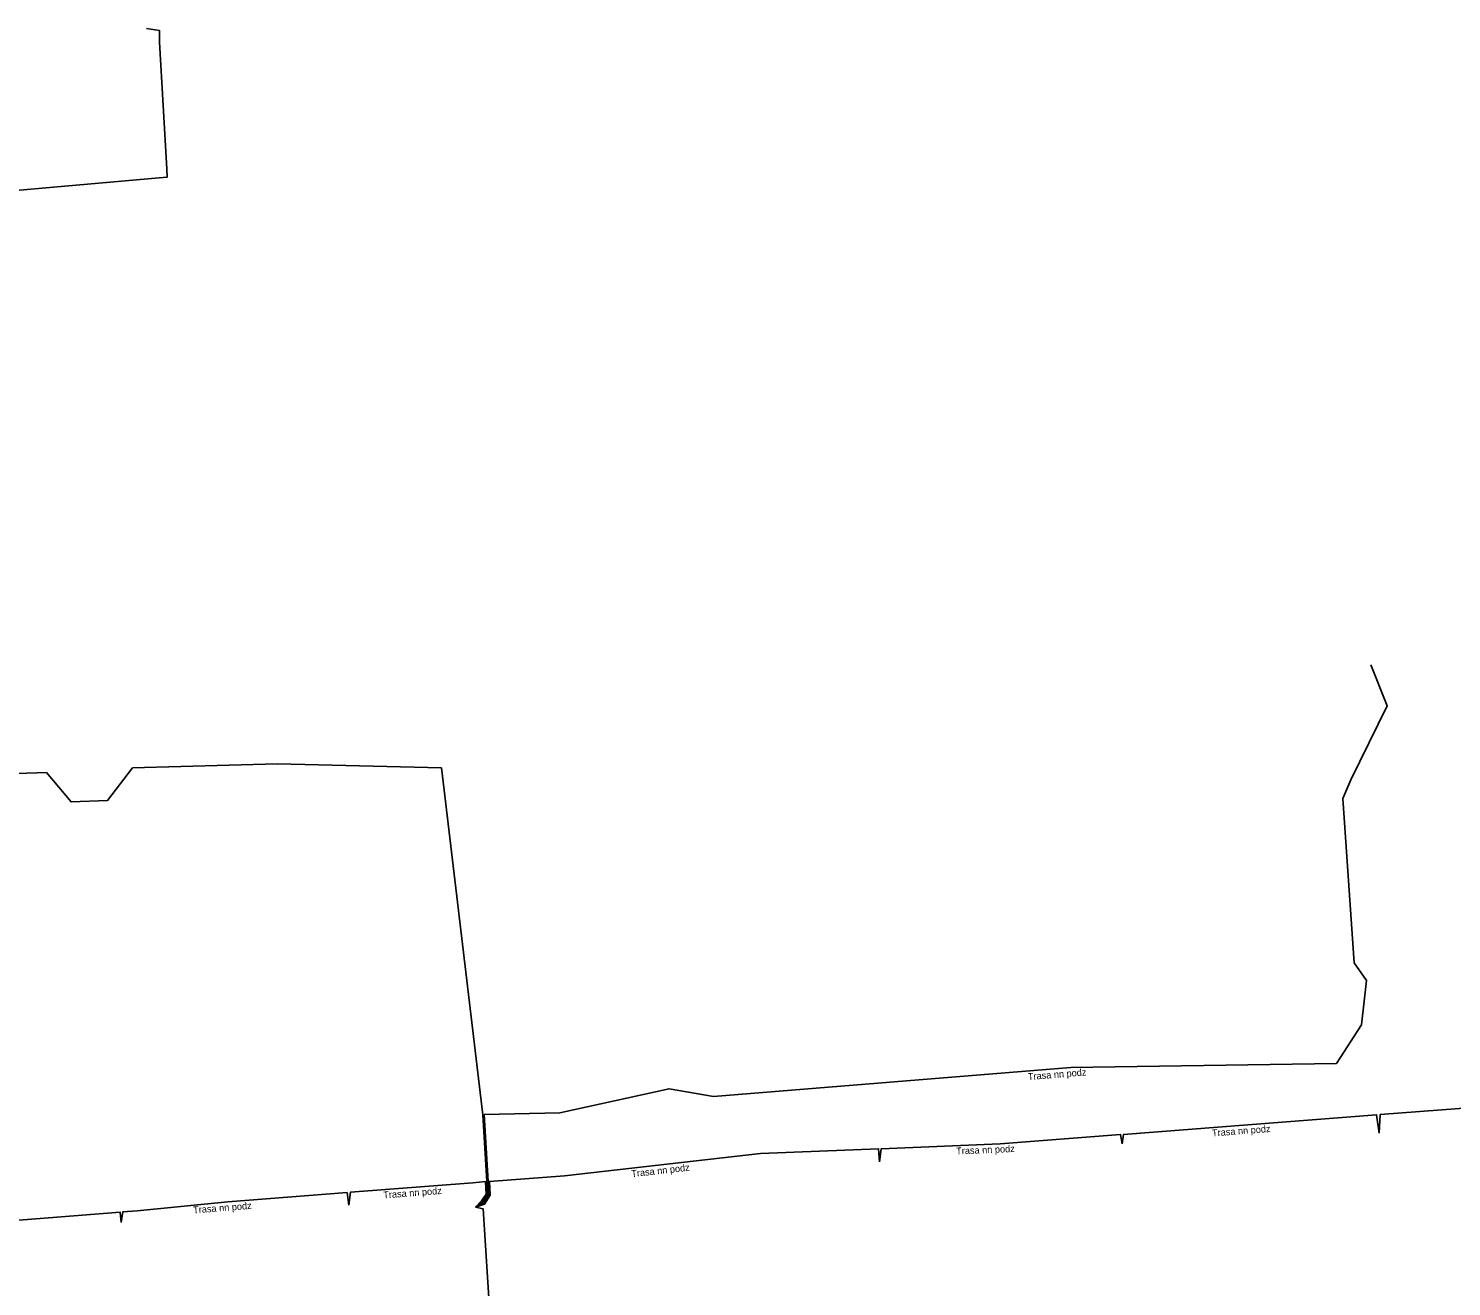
# Model space of a CAD drawing. Extents: x -873583 to -872966, y -1012951 to -1012536.
# Drawn here: x -873321.7 to -873218, y -1012640.4 to -1012548.7 of the extents above; entities that cross this region are included whole.
import ezdxf

# ---------------------------------------------------------------- set-up
doc = ezdxf.new("R2010")
doc.units = 0
doc.layers.add('Popiskový text - Ostatní atributy Trasy', color=7, linetype='Continuous')
doc.layers.add('Spojnice NN', color=7, linetype='Continuous')

msp = doc.modelspace()

# ---------------------------------------------------------------- linework, layer by layer
at = {"layer": 'Spojnice NN'}
for points in [[(-873330.33, -1012561.17), (-873312.15, -1012559.56), (-873311.56, -1012559.51), (-873311.59, -1012558.92), (-873312.14, -1012549.68), (-873312.13, -1012548.83), (-873313.07, -1012548.68)], [(-873289.09, -1012634.63), (-873288.49, -1012634.3), (-873288.13, -1012633.72), (-873288.17, -1012632.75), (-873288.46, -1012627.87), (-873282.96, -1012627.74), (-873274.99, -1012625.99), (-873271.74, -1012626.56), (-873245.69, -1012624.45), (-873226.34, -1012624.15), (-873224.52, -1012621.32), (-873224.14, -1012618.09), (-873225.06, -1012616.8), (-873225.88, -1012604.82), (-873225.28, -1012603.47), (-873222.64, -1012598.07), (-873223.83, -1012595.09)], [(-873289.09, -1012634.63), (-873288.56, -1012634.23), (-873288.23, -1012633.69), (-873288.27, -1012632.76), (-873288.56, -1012627.88), (-873291.58, -1012602.6), (-873303.52, -1012602.29), (-873314.09, -1012602.59), (-873315.91, -1012604.97), (-873318.58, -1012605.07), (-873320.37, -1012602.94), (-873322.5, -1012603)], [(-873223.22, -1012629.23), (-873223.15, -1012627.86), (-873214.48, -1012627.21), (-873204.82, -1012626.51), (-873204.71, -1012627.21)], [(-873241.96, -1012630), (-873241.86, -1012629.32), (-873223.42, -1012627.89), (-873223.22, -1012629.23)], [(-873259.64, -1012631.32), (-873259.52, -1012630.36), (-873250.86, -1012630), (-873242.08, -1012629.33), (-873241.96, -1012630)], [(-873289.09, -1012634.63), (-873288.44, -1012634.41), (-873288.03, -1012633.75), (-873288.07, -1012632.75), (-873282.62, -1012632.33), (-873268.33, -1012630.72), (-873259.72, -1012630.36), (-873259.64, -1012631.32)], [(-873314.92, -1012635.75), (-873314.8, -1012634.96), (-873313.76, -1012634.89), (-873307.16, -1012634.24), (-873298.46, -1012633.56), (-873298.33, -1012634.48)], [(-873298.33, -1012634.48), (-873298.22, -1012633.53), (-873289.3, -1012632.84), (-873288.37, -1012632.76), (-873288.33, -1012633.67), (-873288.67, -1012634.17), (-873289.09, -1012634.63)], [(-873333.86, -1012638.67), (-873334.02, -1012636.47), (-873325.46, -1012635.81), (-873315.01, -1012634.98), (-873314.92, -1012635.75)], [(-873299.89, -1012705.3), (-873300.31, -1012705.31), (-873300.62, -1012705.05), (-873300.65, -1012704.33), (-873300.83, -1012701.17), (-873301.7, -1012684.13), (-873296.38, -1012683.86), (-873295.48, -1012683.78), (-873295.53, -1012683), (-873296.39, -1012671.22), (-873293.71, -1012646.38), (-873288.42, -1012645.97), (-873287.8, -1012645.92), (-873287.85, -1012645.43), (-873288.55, -1012634.74), (-873289.09, -1012634.63)]]:
    msp.add_lwpolyline(points, dxfattribs=at)

# ---------------------------------------------------------------- texts
at = {"layer": 'Popiskový text - Ostatní atributy Trasy'}
for rotation, p in [(4.6307, (-873248.81, -1012625.36)), (4.4265, (-873235.39, -1012629.47)), (2.4355, (-873254.05, -1012630.78)), (6.4355, (-873277.71, -1012632.44)), (4.4152, (-873295.8, -1012633.99)), (4.44, (-873309.66, -1012635.08))]:
    msp.add_text('Trasa nn podz', height=0.5, rotation=rotation, dxfattribs=at).set_placement(p)

doc.saveas('drawing.dxf')
